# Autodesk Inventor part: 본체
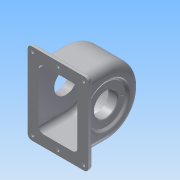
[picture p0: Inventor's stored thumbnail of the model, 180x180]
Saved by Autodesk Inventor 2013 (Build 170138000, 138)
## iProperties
Created: 2015-09
Part Number: 본체
Material: 알루미늄 6061
Document SubType Name: Modeling
Designer: user-11
Density: 2.71 g/cm^3
Mass: 756.275 g
Surface Area: 900.347 cm^2
Volume: 279.068 cm^3
Author: user-11
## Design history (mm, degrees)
sketch "스케치2"
  geometry: L1 (-52, 7)-(52, 7); L2 (52, 7)-(52, 0); L3 (52, 0)-(-52, 0); L4 (-52, 0)-(-52, 7); 1 further point
  constraints: 8 end point, 2 parallel, 1 horizontal, 1 perpendicular
  dimensions: "d0" = 7 distance from line of point (0, 0) L1; "d1" = 0 distance from line of point (0, 0) L3; "d2" = 52 distance from line of point (0, 0) L4; "d3" = 104 distance between parallel lines of L4 L2
extrude "돌출1" new body sketch "스케치2" stored distance "d4" = 140; taper "d5" = 0 deg
node "작업 평면1"
sketch "스케치3"
  geometry: L1 (0, 0)-(140, 0) reference; L2 (0, 7)-(0, 0) reference; L3 (140, 7)-(0, 7) reference; L4 (140, 0)-(140, 7) reference; L5 (70, 0)-(70, 110); L6 (70, 104)-(79.701, 104); L7 (70, 47)-(96.584, 47); L8 (13, 47)-(13, 7); L9 (127, 47)-(127, 7); A1 r 57 centre (70, 47) between (127, 47) and (13, 47)
  constraints: 10 end point, 5 point on line, 3 parallel, 3 point on circle, 2 perpendicular, 2 tangent, 1 centre point, 1 coincident
  dimensions: "d6" = 110 distance of L5.start L5.end; "d7" = 6 distance from line of L5.end L6; "d8" = 47 distance between parallel lines of L1 L7
extrude "돌출2" join sketch "스케치3" stored distance "d9" = 77; taper "d10" = 0 deg
node "작업 평면2"
sketch "스케치4"
  geometry: L1 (-127, 7)-(-127, 47) reference; L2 (-13, 47)-(-13, 7) reference; L3 (-121, 47)-(-121, 0); L4 (-19, 47)-(-19, 0); L5 (0, 0)-(-140, 0) reference; A1 r 57 centre (-70, 47) between (-13, 47) and (-127, 47) reference; A2 r 51 centre (-70, 47) between (-19, 47) and (-121, 47); 1 further point
  constraints: 4 end point, 3 parallel, 2 point on circle, 2 point on line, 1 centre point, 1 coincident, 1 tangent
  dimensions: "d11" = 51 distance from line of point (-70, 0) L3; "d12" = 102 distance between parallel lines of L3 L4
extrude "돌출3" cut sketch "스케치4" stored distance "d13" = 67; taper "d14" = 0 deg
node "작업 평면3"
sketch "스케치5"
  geometry: L1 (-38.5, 104)-(-38.5, 47) reference; L2 (-38.5, 47)-(-38.5, 7) reference; L3 (-33.5, 47)-(-33.5, 0) reference; L4 (-33.5, 98)-(-33.5, 47) reference; L5 (33.5, 47)-(33.5, 98) reference; L6 (33.5, 0)-(33.5, 47) reference; L7 (38.5, 7)-(38.5, 47) reference; L8 (38.5, 47)-(38.5, 104) reference; L9 (-49.023, 47)-(65.763, 47); L10 (-19.5, 67)-(-19.5, 75); L11 (-19.5, 75)-(-33.5, 86.747); L12 (-19.5, 67)-(-33.5, 67); L13 (48.5, 47)-(48.5, 78); L14 (48.5, 78)-(38.5, 78); L15 (48.5, 47)-(38.5, 47); 1 further point
  constraints: 14 end point, 5 perpendicular, 4 point on line
  dimensions: "d15" = 47 distance from line of point (0, 0) L9; "d16" = 40 diameter of L12 L9; "d17" = 56 diameter of L10.end L9; "d18" = 50 deg angle of L4 L11; "d19" = 10 distance between parallel lines of L8 L13; "d20" = 62 diameter of L14 L9; "d21" = 19 distance between parallel lines of L1 L10
revolve "회전1" sketch "스케치5" stored, may be unused: angle "d22" = 90 deg
sketch "스케치6"
  geometry: C1 r 31 at (0, 0) reference; C2 r 20 at (0, 0); 1 further point
  constraints: 1 centre point, 1 coincident
  dimensions: "d23" = 40 diameter of C2
extrude "돌출4" cut sketch "스케치6" stored distance "d25" = 67; taper "d26" = 0 deg
sketch "스케치7"
  geometry: L1 (-33.5, 86.747)-(-19.5, 75) reference; L2 (-33.5, 7.253)-(-19.5, 19) reference; L3 (-35.5, 80)-(-35.5, 67); L4 (-19.5, 27)-(-19.5, 67) reference; L5 (-38.5, 84.416)-(-33.237, 80); L6 (-19.5, 19)-(-19.5, 75) reference; L7 (-38.5, 104)-(-38.5, 47) reference; L8 (-38.5, 27)-(-38.5, 67) reference; L9 (-38.5, 47)-(-38.5, 7) reference; L10 (-66.176, 47)-(7.982, 47); L11 (33.5, 0)-(-33.5, 0) reference; L12 (-35.5, 80)-(-33.237, 80); L13 (-19.5, 67)-(-38.5, 67) reference; 1 further point
  constraints: 8 end point, 2 parallel, 2 point on line, 1 perpendicular, 1 vertical
  dimensions: "d27" = 16 distance between parallel lines of L4 L3; "d28" = 5 distance between parallel lines of L1 L5; "d29" = 47 distance between parallel lines of L11 L10; "d30" = 66 diameter of L3.start L10
revolve "회전2" sketch "스케치7" stored, may be unused: angle "d31" = 90 deg
sketch "스케치8"
  geometry: C1 r 20 at (0, 0) reference; C2 r 28 at (0, 0); C3 r 5.258 at (0, 28); 1 further point
  constraints: 2 centre point, 1 coincident
  dimensions: "d32" = 56 diameter of C2
hole "구멍1" sketch "스케치8" at (0, 28) diameter "d34" = 2.459; stored, may be unused: countersink angle "d38" = 90 deg, drill point angle "d40" = 118 deg; dims "d35" = 7, "d36" = 4, "d37" = 2, "d39" = 9
sketch "스케치9" dims "d44" = 48
  geometry: C1 r 31 at (0, 0) reference; C2 r 2.394 at (0, 24); 2 further points
  constraints: 1 centre point, 1 coincident, 1 vertical alignment, 2 other
hole "구멍2" sketch "스케치9" at (0, 24) diameter "d46" = 2.459; stored, may be unused: countersink angle "d50" = 90 deg, drill point angle "d52" = 118 deg; dims "d47" = 6, "d48" = 4, "d49" = 2, "d51" = 8
node "작업 평면4"
sketch "스케치10"
  geometry: L1 (0, 0)-(0, 110); L2 (38.5, 104)-(-38.5, 104) reference; L3 (-33.5, 98)-(33.5, 98) reference; L4 (0, 110)-(-6, 110); L5 (-6, 110)-(-7.886, 99.307); L6 (-7.886, 99.307)-(0, 99.307)
  constraints: 8 end point, 1 parallel, 1 perpendicular, 1 point on line, 1 vertical
  dimensions: "d62" = 110 distance of L1.start L1.end; "d63" = 12 diameter of L4.end L1; "d64" = 100 deg angle of L6 L5
revolve "회전3" sketch "스케치10" stored, may be unused: angle "d65" = 90 deg
sketch "스케치11"
  geometry: C1 r 6 at (0, 0) reference
hole "구멍3" sketch "스케치11" at (0, 0) diameter "d66" = 4.134; stored, may be unused: countersink angle "d70" = 90 deg, drill point angle "d72" = 118 deg; dims "d67" = 15, "d68" = 4, "d69" = 2, "d71" = 8
sketch "스케치12"
  geometry: L1 (77, 0)-(77, -40) reference; L2 (38.5, -47)-(38.5, 77.946); L3 (28.206, -17)-(38.5, -17); L4 (-13.5, -47)-(90.5, -47) reference; L5 (13.613, -13.398)-(63.387, -13.398); L6 (63.387, -13.398)-(63.387, -20.602); L7 (63.387, -20.602)-(13.613, -20.602); L8 (13.613, -20.602)-(13.613, -13.398); L9 (13.613, -13.398)-(63.387, -20.602); L10 (63.387, -13.398)-(13.613, -20.602); L11 (38.5, -17)-(38.604, -21.845)
  constraints: 10 end point, 1 midpoint, 1 parallel, 1 perpendicular, 1 point on line, 2 other
  dimensions: "d73" = 30 distance between parallel lines of L4 L3; "d74" = 0 distance of L3.end L11.start; "d75" = 0 distance of L3.end L11.start
extrude "돌출5" join sketch "스케치12" distance "d76" = 0.5; taper "d77" = 0 deg
fillet "모깎기2" dims "d79" = 3
fillet "모깎기3" dims "d80" = 0.5
fillet "모깎기4" dims "d81" = 3
fillet "모깎기5" dims "d82" = 3
fillet "모깎기7" dims "d84" = 7
sketch "스케치13"
  geometry: L1 (97, -133)-(97, -7) reference; L2 (0, 0)-(90, 0) reference; L3 (-7, -7)-(-7, -133) reference; L4 (90, -140)-(0, -140) reference; L5 (84.5, -12)-(5.5, -12) reference; L6 (1, 9.606)-(1, -153.708); L7 (-16.915, -8)-(110.248, -8); L8 (89, 4.478)-(89, -155.246); L9 (-20.761, -132)-(107.428, -132); L10 (45, -70)-(45, 24.075); L11 (45, -70)-(45, -183.978); C1 r 2.5 at (1, -8); C2 r 2.5 at (89, -8); C3 r 2.5 at (89, -132); C4 r 2.5 at (1, -132); C5 r 2.5 at (45, -132); C6 r 2.5 at (45, -8); 2 further points
  constraints: 12 end point, 12 point on line, 6 centre point, 5 perpendicular, 1 collinear
  dimensions: "d85" = 8 distance between parallel lines of L3 L6; "d87" = 8 distance between parallel lines of L2 L7; "d88" = 8 distance between parallel lines of L4 L9; "d89" = 8 distance between parallel lines of L1 L8; "d90" = 5 diameter of C4; "d91" = 5 diameter of C5; "d92" = 5 diameter of C3; "d93" = 5 diameter of C1; "d94" = 5 diameter of C2; "d95" = 5 diameter of C6
extrude "돌출6" cut sketch "스케치13" stored distance "d96" = 0.5; taper "d97" = 0 deg
fillet "모깎기8" dims "d98" = 3
chamfer "모따기1" distance "d99" = 1; stored, may be unused: second distance "d100" = 2, angle "d101" = 45 deg
chamfer "모따기2" distance "d102" = 1; stored, may be unused: second distance "d103" = 2, angle "d104" = 45 deg
fillet "모깎기9" dims "d105" = 14
fillet "모깎기10" dims "d106" = 9
fillet "모깎기11" dims "d107" = 1
node "솔리드1"
pattern_circular "원형 패턴1" dims angle "d42" = 360 deg
pattern_circular "원형 패턴2" dims angle "d54" = 360 deg
node "투영된 루프1"
